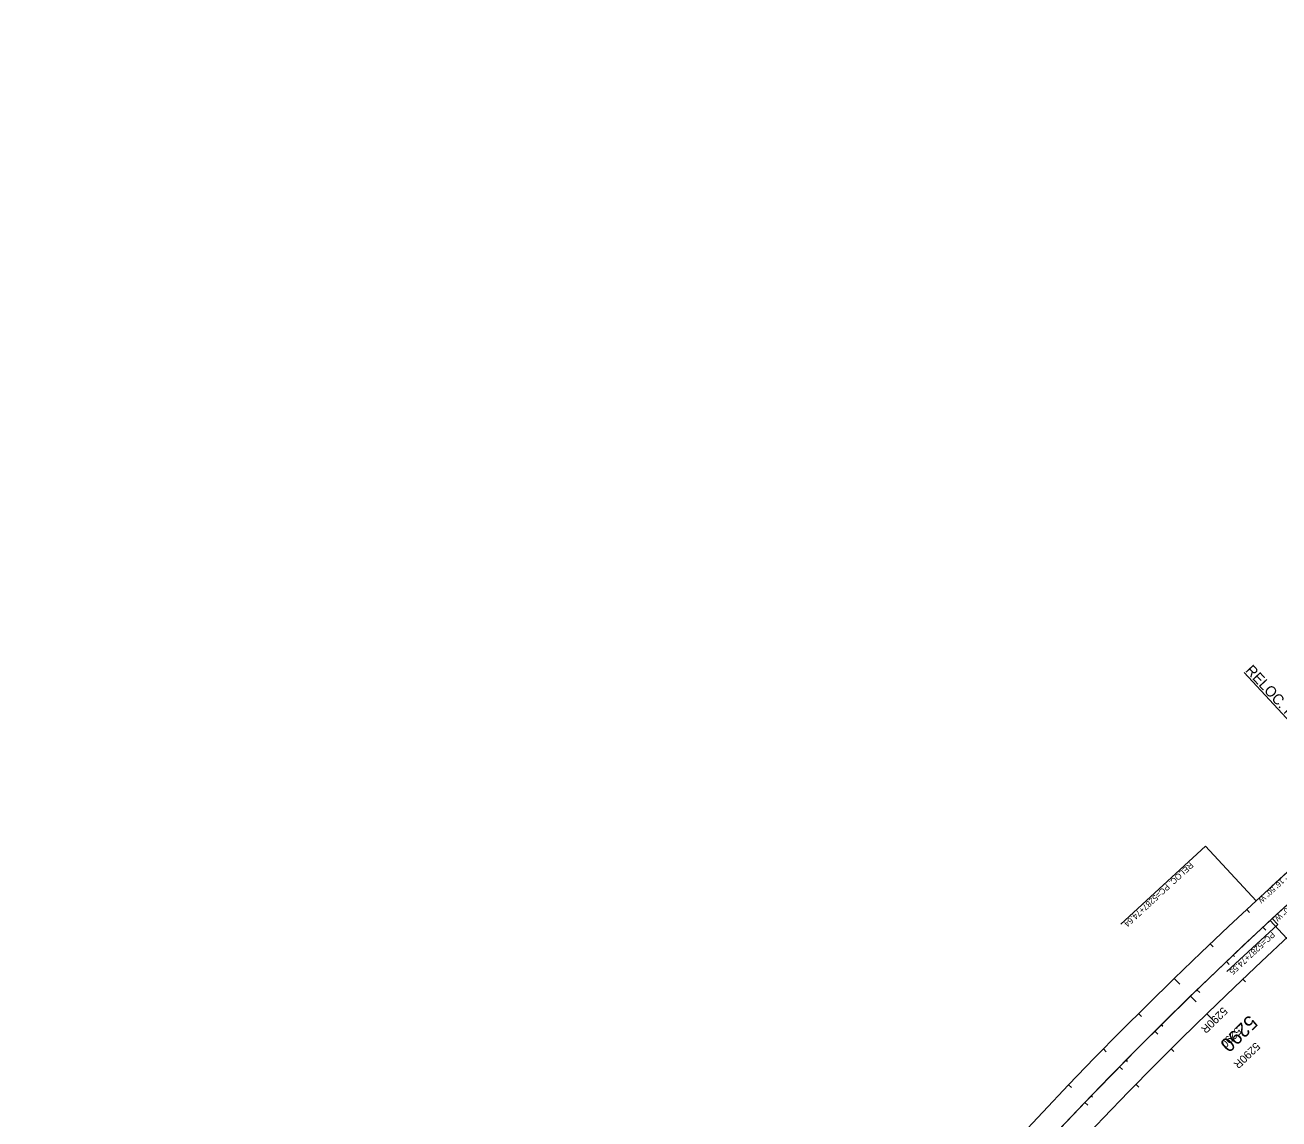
# Model space of a CAD drawing. Extents: x 2160876 to 2175990, y 601436 to 618246.
# Drawn here: x 2161211 to 2163718, y 605458 to 607646 of the extents above; entities that cross this region are included whole.
import ezdxf

# ---------------------------------------------------------------- set-up
doc = ezdxf.new("R2010")
doc.units = 0
for name, color, linetype in [('BNDY-ADJ', 7, 'Continuous'), ('BNDY-ADJ-TXT', 7, 'Continuous'), ('RD_DTM_Major2', 7, 'Continuous'), ('RD_EX_BldgApp_Steps', 7, 'Continuous'), ('RD_EX_DV_TX_Prop', 7, 'Continuous'), ('RD_EX_Parking_Conc', 7, 'Continuous'), ('RD_HC_Cl', 7, 'Continuous'), ('RD_HC_Data_Tic', 7, 'Continuous'), ('RD_HC_TX_Sta50', 7, 'Continuous')]:
    doc.layers.add(name, color=color, linetype=linetype)

msp = doc.modelspace()

# ---------------------------------------------------------------- linework, layer by layer
at = {"layer": 'BNDY-ADJ'}
msp.add_line((2172239.9, 613739.9), (2163704.8, 605858.6), dxfattribs=at)
msp.add_arc((2169535, 599544.7), 8593.9, 132.71947, 164.41949, dxfattribs=at)
at = {"layer": 'BNDY-ADJ-TXT'}
msp.add_line((2163817.9, 606028.4), (2163672.2, 605893.8), dxfattribs=at)
for radius in [8641.9, 8545.9]:
    msp.add_arc((2169535, 599544.7), radius, 132.71947, 164.41949, dxfattribs=at)
at = {"layer": 'RD_DTM_Major2'}
for p, q in [((2163686.1, 605841.3), (2163691.6, 605835.4)), ((2163613.3, 605772.8), (2163618.8, 605767)), ((2163541.2, 605703.5), (2163552.4, 605692)), ((2163469.9, 605633.3), (2163475.6, 605627.6)), ((2163399.5, 605562.3), (2163405.2, 605556.7)), ((2163329.9, 605490.5), (2163335.7, 605485))]:
    msp.add_line(p, q, dxfattribs=at)
at = {"layer": 'RD_EX_BldgApp_Steps'}
for p, q in [((2172672.7, 614139.6), (2163700.6, 605854.7)), ((2163648.5, 606351.1), (2163887.2, 606092.6)), ((2163887.2, 606092.6), (2163703.5, 605923)), ((2163700.6, 605854.7), (2163893, 605646.3)), ((2163626.5, 605785.4), (2163629.2, 605782.5)), ((2163554.2, 605716.3), (2163559.8, 605710.5)), ((2163482.7, 605646.3), (2163485.6, 605643.5)), ((2163412.1, 605575.5), (2163415, 605572.7)), ((2163342.3, 605503.9), (2163345.2, 605501.1))]:
    msp.add_line(p, q, dxfattribs=at)
msp.add_arc((2169530.8, 599540.9), 8593.9, 132.71947, 164.42145, dxfattribs=at)
at = {"layer": 'RD_EX_Parking_Conc'}
for p, q in [((2163715.7, 605846.8), (2163613.6, 605752.5)), ((2163704.8, 605858.6), (2163715.7, 605846.8))]:
    msp.add_line(p, q, dxfattribs=at)
at = {"layer": 'RD_HC_Cl'}
for p, q in [((2163653.6, 605876.6), (2163659.1, 605870.7)), ((2163580.8, 605808.1), (2163586.3, 605802.3)), ((2163508.7, 605738.8), (2163519.8, 605727.3)), ((2163645.9, 605737.6), (2163651.4, 605731.8)), ((2163437.4, 605668.6), (2163443.1, 605663)), ((2163573.8, 605668.2), (2163585, 605656.8)), ((2163367, 605597.7), (2163372.7, 605592.1)), ((2163502.6, 605598.1), (2163508.2, 605592.4)), ((2163297.3, 605525.9), (2163303.1, 605520.4)), ((2163432.2, 605527.1), (2163437.9, 605521.5))]:
    msp.add_line(p, q, dxfattribs=at)
at = {"layer": 'RD_HC_TX_Sta50'}
for q in [(2163402.1, 605847.4), (2163672.2, 605893.8)]:
    msp.add_line((2163571, 606003.4), q, dxfattribs=at)

# ---------------------------------------------------------------- texts
at = {"layer": 'RD_EX_BldgApp_Steps'}
for s, height, rotation, p in [('RELOC. PT=5285+00.05', 21, 312.7195, (2163649.8, 606354.1)), ('5290', 28, 224.0629, (2163658.7, 605667.1))]:
    msp.add_text(s, height=height, rotation=rotation, dxfattribs=at).set_placement(p)
at = {"layer": 'RD_EX_DV_TX_Prop'}
msp.add_text('5290', height=16, rotation=224.2225, dxfattribs=at).set_placement((2163633.8, 605642.9))
at = {"layer": 'RD_EX_Parking_Conc'}
for s, height, p in [('S 47° 16\' 50" W', 10.8, (2163785.5, 605930.9)), ('PC=5287+74.55', 12, (2163703.5, 605833.3))]:
    msp.add_text(s, height=height, rotation=222.7195, dxfattribs=at).set_placement(p)
at = {"layer": 'RD_HC_Data_Tic'}
for rotation, p in [(224.2136, (2163606, 605682.8)), (224.2304, (2163671.2, 605612.3))]:
    msp.add_text('5290R', height=16, rotation=rotation, dxfattribs=at).set_placement(p)
at = {"layer": 'RD_HC_TX_Sta50'}
for s, height, p in [('RELOC. PC=5287+74.64', 12, (2163540.2, 605972.3)), ('S 47° 16\' 50" W', 10.8, (2163752.5, 605967.1))]:
    msp.add_text(s, height=height, rotation=222.7195, dxfattribs=at).set_placement(p)

doc.saveas('drawing.dxf')
